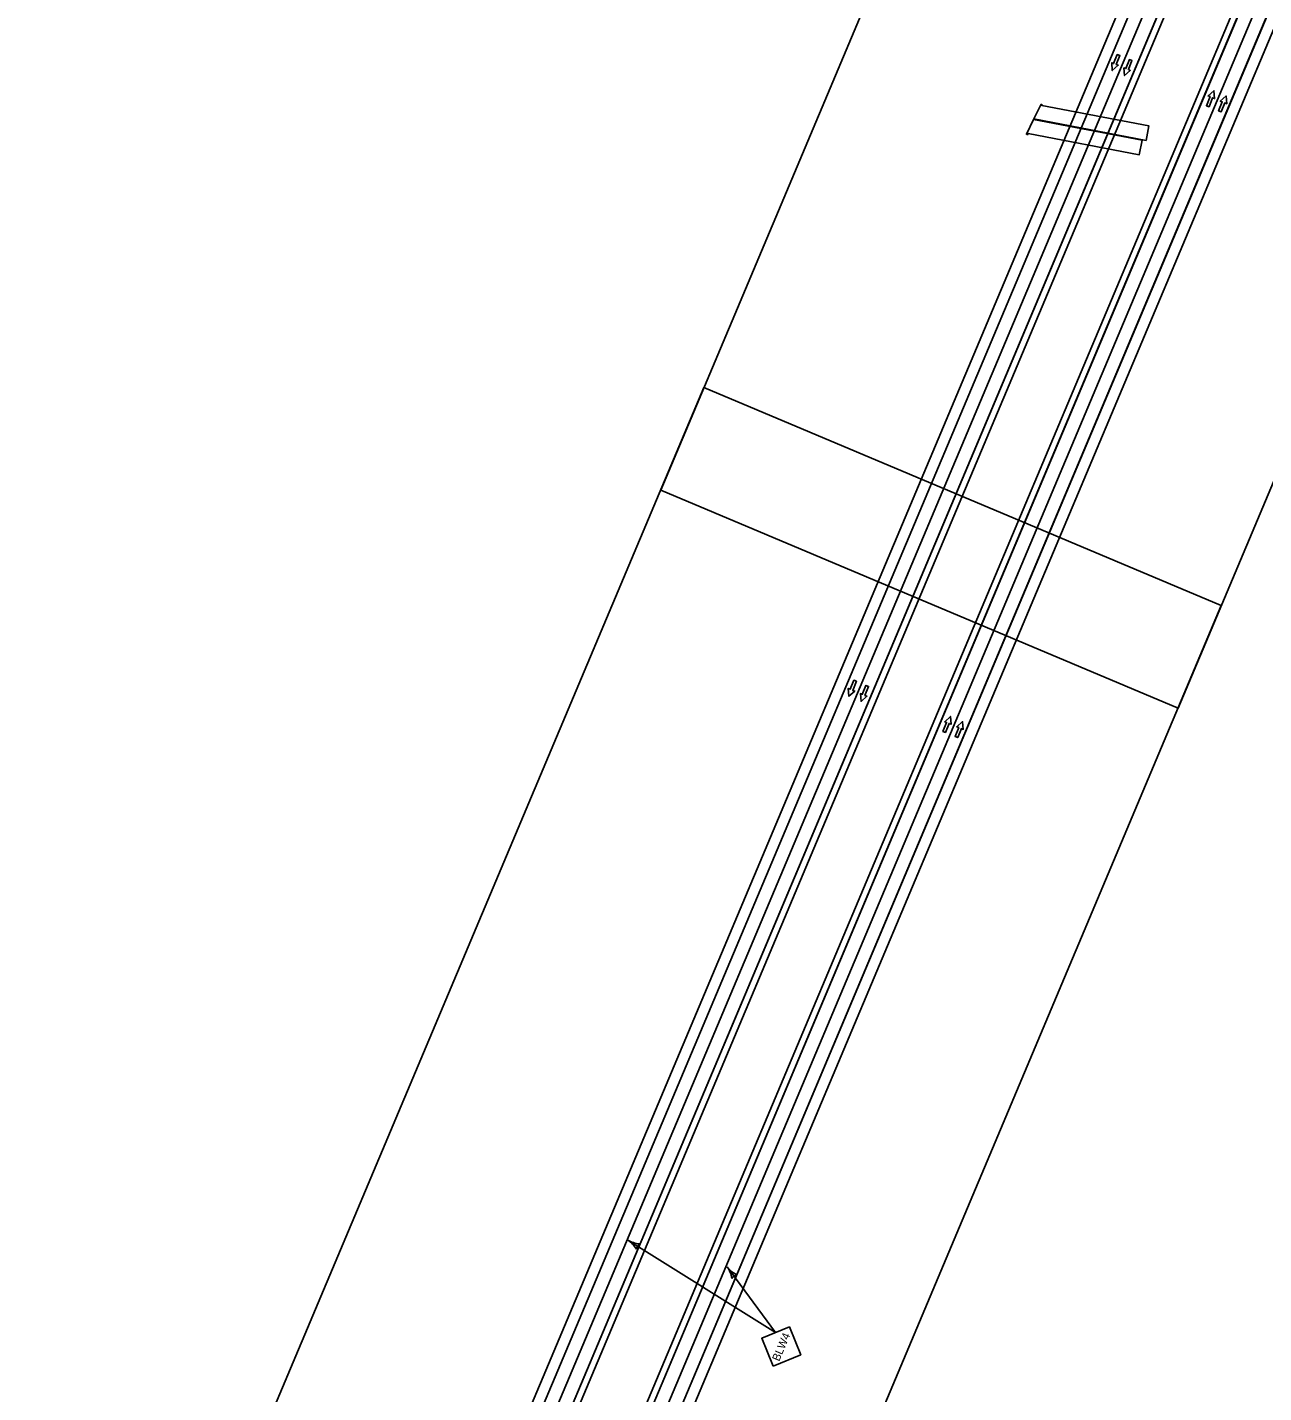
# Model space of a CAD drawing. Extents: x 14107086 to 14122011, y 8637163 to 8671583.
# Drawn here: x 14108941 to 14110053, y 8646064 to 8647292 of the extents above; entities that cross this region are included whole.
import ezdxf

# ---------------------------------------------------------------- set-up
doc = ezdxf.new("R2010")
doc.units = 0
for name, color, linetype in [('dsn_culvert_prop', 7, 'Continuous'), ('dsnNonPlotable', 7, 'Continuous'), ('dsnPaintExistingBrokenLaneLineWhite', 7, 'Continuous'), ('dsnPaintExistingEdgeLineLeftYellow', 7, 'Continuous'), ('dsnPaintExistingEdgeLineRightWhite', 7, 'Continuous'), ('dsnPaintPlaceBrokenLaneWhite', 7, 'Continuous'), ('dsnPaintRemoveDoubleCenterLineYellow', 7, 'Continuous'), ('dsnShadingPaved', 7, 'Continuous'), ('dsnStdLabel', 7, 'Continuous'), ('dsnStgShadingPrevPav', 7, 'Continuous'), ('Level 2', 7, 'Continuous'), ('Level 5', 7, 'Continuous')]:
    doc.layers.add(name, color=color, linetype=linetype)

msp = doc.modelspace()

# ---------------------------------------------------------------- linework, layer by layer
at = {"layer": 'dsn_culvert_prop'}
for points in [[(14109852.4, 8647223.3), (14109853.3, 8647222.8), (14109853, 8647222.2), (14109949.4, 8647203.7), (14109946.9, 8647190.6), (14109845.9, 8647210)], [(14109845.7, 8647209.5), (14109839.2, 8647196.2), (14109840.1, 8647195.7), (14109840.7, 8647196.9), (14109940.7, 8647177.7), (14109943.3, 8647190.8)]]:
    msp.add_lwpolyline(points, close=True, dxfattribs=at)
at = {"layer": 'dsnNonPlotable'}
for points in [[(14109510.3, 8646876.1), (14110118.8, 8648320.7), (14110584.2, 8648124.6), (14109975.6, 8646680.1)], [(14108940.5, 8645523.8), (14109549.1, 8646968.3), (14110014.5, 8646772.2), (14109405.9, 8645327.7)]]:
    msp.add_lwpolyline(points, close=True, dxfattribs=at)
at = {"layer": 'dsnPaintExistingBrokenLaneLineWhite'}
msp.add_line((14109153.7, 8645426.8), (14110829.5, 8649404.5), dxfattribs=at)
at = {"layer": 'dsnPaintExistingEdgeLineLeftYellow'}
for p, q in [((14110840.5, 8649399.8), (14109233.5, 8645585.3)), ((14109318.5, 8645614.6), (14110902.3, 8649373.8))]:
    msp.add_line(p, q, dxfattribs=at)
at = {"layer": 'dsnPaintExistingEdgeLineRightWhite'}
for p, q in [((14110818.4, 8649409.2), (14109217, 8645608.1)), ((14109248.6, 8645386.8), (14110924.4, 8649364.5))]:
    msp.add_line(p, q, dxfattribs=at)
at = {"layer": 'dsnPaintPlaceBrokenLaneWhite'}
for p, q in [((14110829.5, 8649404.5), (14109153.7, 8645426.8)), ((14109237.5, 8645391.4), (14110913.3, 8649369.2))]:
    msp.add_line(p, q, dxfattribs=at)
at = {"layer": 'dsnPaintRemoveDoubleCenterLineYellow'}
msp.add_line((14110829.5, 8649404.5), (14109153.7, 8645426.8), dxfattribs=at)
at = {"layer": 'dsnShadingPaved'}
for p, q in [((14109142.6, 8645431.4), (14110818.4, 8649409.2)), ((14110840.5, 8649399.8), (14109164.7, 8645422.1))]:
    msp.add_line(p, q, dxfattribs=at)
msp.add_lwpolyline([(14109248.6, 8645386.8), (14116822, 8663369.3), (14116799.9, 8663378.6), (14109226.5, 8645396.1)], close=True, dxfattribs=at)
at = {"layer": 'dsnStdLabel'}
for q in [(14109480.6, 8646201.6), (14109570.1, 8646177.4)]:
    msp.add_line((14109613.6, 8646118.3), q, dxfattribs=at)
msp.add_lwpolyline([(14109611.3, 8646088.2), (14109636.3, 8646098.4), (14109626.1, 8646123.4), (14109601.1, 8646113.2)], close=True, dxfattribs=at)
for centre, radius, start, end in [((14109468.5, 8646182.1), 22.9, 29.8729, 57.9442), ((14109492.8, 8646221), 22.9, 237.944, 266.0153), ((14109497, 8646191.3), 8.86, 130.2099, 165.6783), ((14109551.6, 8646163.8), 22.9, 8.2866, 36.3579), ((14109588.6, 8646191), 22.9, 216.3578, 244.429), ((14109581.5, 8646161.9), 8.86, 108.6236, 144.092)]:
    msp.add_arc(centre, radius, start, end, dxfattribs=at)
at = {"layer": 'dsnStgShadingPrevPav'}
for p, q in [((14109133.4, 8645435.3), (14110809.2, 8649413)), ((14110818.4, 8649409.2), (14109142.6, 8645431.4))]:
    msp.add_line(p, q, dxfattribs=at)
for points in [[(14109239, 8645583), (14111389.1, 8650687.1), (14111383.6, 8650689.4), (14109233.5, 8645585.3)], [(14109313, 8645616.9), (14110622.7, 8648725.7), (14110659.7, 8648710.5), (14109349.9, 8645601.4)]]:
    msp.add_lwpolyline(points, close=True, dxfattribs=at)
at = {"layer": 'Level 2'}
for points in [[(14109923.3, 8647267), (14109921, 8647267.9), (14109917.7, 8647259.8), (14109916, 8647260.5), (14109916.5, 8647253.5), (14109921.8, 8647258.2), (14109920, 8647258.9)], [(14109934.2, 8647262.4), (14109931.9, 8647263.3), (14109928.7, 8647255.2), (14109926.9, 8647255.9), (14109927.5, 8647248.9), (14109932.7, 8647253.6), (14109931, 8647254.3)], [(14110001.1, 8647221.8), (14110003.5, 8647220.9), (14110006.7, 8647229), (14110008.5, 8647228.3), (14110007.9, 8647235.3), (14110002.7, 8647230.7), (14110004.4, 8647230)], [(14110012.1, 8647217.2), (14110014.4, 8647216.3), (14110017.7, 8647224.4), (14110019.4, 8647223.7), (14110018.9, 8647230.7), (14110013.6, 8647226.1), (14110015.4, 8647225.3)], [(14109686.3, 8646704.2), (14109684, 8646705.1), (14109680.7, 8646697), (14109679, 8646697.7), (14109679.5, 8646690.7), (14109684.8, 8646695.3), (14109683, 8646696)], [(14109697.2, 8646699.6), (14109694.9, 8646700.5), (14109691.6, 8646692.4), (14109689.9, 8646693.1), (14109690.5, 8646686.1), (14109695.7, 8646690.7), (14109694, 8646691.4)], [(14109764.1, 8646659), (14109766.4, 8646658.1), (14109769.7, 8646666.2), (14109771.5, 8646665.5), (14109770.9, 8646672.5), (14109765.7, 8646667.8), (14109767.4, 8646667.1)], [(14109775.1, 8646654.4), (14109777.4, 8646653.5), (14109780.7, 8646661.6), (14109782.4, 8646660.9), (14109781.8, 8646667.9), (14109776.6, 8646663.2), (14109778.3, 8646662.5)]]:
    msp.add_lwpolyline(points, close=True, dxfattribs=at)
at = {"layer": 'Level 5'}
for points in [[(14109920, 8647258.9), (14109921.8, 8647258.2), (14109916.5, 8647253.5), (14109916, 8647260.5), (14109917.7, 8647259.8), (14109921, 8647267.9), (14109923.3, 8647267), (14109920, 8647258.9)], [(14109931, 8647254.3), (14109932.7, 8647253.6), (14109927.5, 8647248.9), (14109926.9, 8647255.9), (14109928.7, 8647255.2), (14109931.9, 8647263.3), (14109934.2, 8647262.4), (14109931, 8647254.3)], [(14110004.4, 8647230), (14110002.7, 8647230.7), (14110007.9, 8647235.3), (14110008.5, 8647228.3), (14110006.7, 8647229), (14110003.5, 8647220.9), (14110001.1, 8647221.8), (14110004.4, 8647230)], [(14110015.4, 8647225.3), (14110013.6, 8647226.1), (14110018.9, 8647230.7), (14110019.4, 8647223.7), (14110017.7, 8647224.4), (14110014.4, 8647216.3), (14110012.1, 8647217.2), (14110015.4, 8647225.3)], [(14109683, 8646696), (14109684.8, 8646695.3), (14109679.5, 8646690.7), (14109679, 8646697.7), (14109680.7, 8646697), (14109684, 8646705.1), (14109686.3, 8646704.2), (14109683, 8646696)], [(14109694, 8646691.4), (14109695.7, 8646690.7), (14109690.5, 8646686.1), (14109689.9, 8646693.1), (14109691.6, 8646692.4), (14109694.9, 8646700.5), (14109697.2, 8646699.6), (14109694, 8646691.4)], [(14109767.4, 8646667.1), (14109765.7, 8646667.8), (14109770.9, 8646672.5), (14109771.5, 8646665.5), (14109769.7, 8646666.2), (14109766.4, 8646658.1), (14109764.1, 8646659), (14109767.4, 8646667.1)], [(14109778.3, 8646662.5), (14109776.6, 8646663.2), (14109781.8, 8646667.9), (14109782.4, 8646660.9), (14109780.7, 8646661.6), (14109777.4, 8646653.5), (14109775.1, 8646654.4), (14109778.3, 8646662.5)]]:
    msp.add_lwpolyline(points, dxfattribs=at)

# ---------------------------------------------------------------- texts
at = {"layer": 'dsnStdLabel'}
msp.add_text('BLW4', height=7.2, rotation=67.1547, dxfattribs=at).set_placement((14109616.8, 8646092))

doc.saveas('drawing.dxf')
